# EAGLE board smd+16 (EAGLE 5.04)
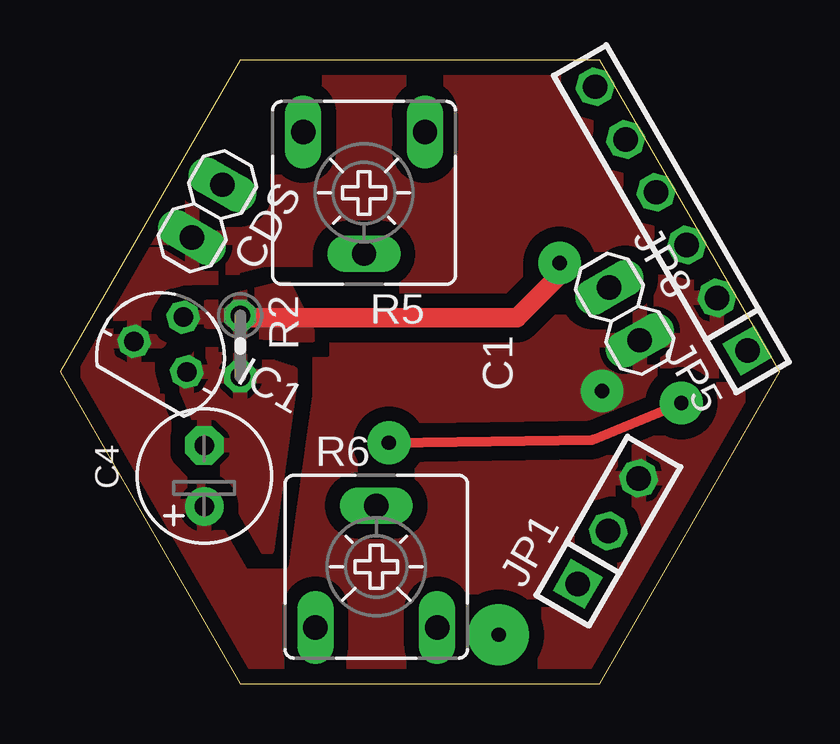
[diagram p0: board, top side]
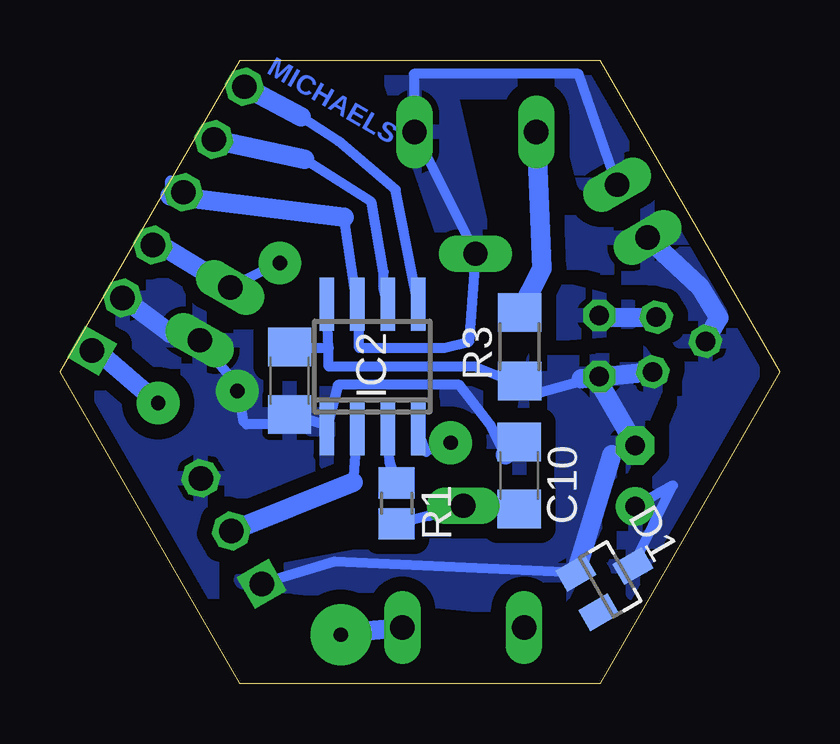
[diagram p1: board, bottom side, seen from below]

Size 30 x 25.98 mm. Coordinates in mm from the lower left corner, seen from the top.
Outline: 7.5,0 22.5,0 30,12.99 22.5,25.98 7.5,25.98 0,12.99 7.5,0
Copper layers (1*16): Top 0.035mm / dielectric 1.5mm / Bottom 0.035mm
Design rules "default *": minimum track width 10mil, minimum drill 24mil, track to track 8mil, track to pad 8mil, pad to pad 8mil, via to via 8mil, smd to smd 8mil, copper to edge 10mil, drill to drill 8mil, minimum pad ring 10mil, minimum via ring 8mil, stop-mask expansion 4mil, vias tented up to drill 0mil, thermal gap 10mil

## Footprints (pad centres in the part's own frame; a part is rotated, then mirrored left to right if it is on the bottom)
C1206 = smd 1.6 x 1.8: 1 -1.4,0; 2 1.4,0
E2,5-6 = drill 0.813 pad 1.6 round: + -1.27,0 | drill 0.813 pad 1.6 octagon: - 1.27,0
1X02 = drill 1.016 long: 1 -1.27,0; 2 1.27,0
SOT23 = smd 1 x 1.4: 1 -0.95,-1.1; 2 0.95,-1.1; 3 0,1.1
79LXX = drill 0.813 octagon: GND -1.27,0; IN 0,1.905; OUT 1.27,0
SO-08 = smd 0.6 x 2.2: 1 -1.905,-2.6; 2 -0.635,-2.6; 3 0.635,-2.6; 4 1.905,-2.6; 5 1.905,2.6; 6 0.635,2.6; 7 -0.635,2.6; 8 -1.905,2.6
1X03 = drill 1.016 square: 1 -2.54,0 | drill 1.016 octagon: 2 0,0; 3 2.54,0
1X06 = drill 1.016 square: 1 -6.35,0 | drill 1.016 octagon: 2 -3.81,0; 3 -1.27,0; 4 1.27,0; 5 3.81,0; 6 6.35,0
R0805 = smd 1.3 x 1.5: 1 -0.85,0; 2 0.85,0
0204V = drill 0.813 octagon: 1 -1.27,0; 2 1.27,0
R1206 = smd 1.6 x 1.803: 1 -1.422,0; 2 1.422,0
CA6V = drill 1.016 long: A -2.54,-2.54; E 2.54,-2.54; S 0,2.54

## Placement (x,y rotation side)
C1  0u1  [C1206]  20.42,12.62 270 bottom
C4  47u 10  [E2,5-6]  6.02,8.65 90 top
C10  0u1  [C1206]  10.85,8.66 270 bottom
CDS  [1X02]  6.14,19.68 240 top
D1  [SOT23]  7.06,4.34 300 bottom
IC1  [79LXX]  4.19,13.62 330 top
IC2  PIC12F629SN  [SO-08]  16.98,13.2 0 bottom
JP1  [1X03]  22.86,6.35 60 top
JP5  [1X06]  25.48,19.37 120 top
JP8  [1X02]  23.54,15.4 300 top
R1  150k  [R0805]  15.96,7.51 270 bottom
R2  150k  [0204V]  7.51,14.06 270 top
R3  680k  [R1206]  10.84,14.03 90 bottom
R5  500k  [CA6V]  12.68,20.45 180 top
R6  [CA6V]  13.19,4.87 0 top

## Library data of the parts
C1 C4 C10 R1-R3 = rcl
CDS JP8 = pinhead
D1 = diode-1
IC1 = v-reg
IC2 = microchip-3
JP1 JP5 = pinhead(2)
R5 R6 = pot

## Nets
CDS: IC2.2 JP1.2
N$1: C10.2 R1.2 R6.S
N$2: IC2.5 JP5.6
N$3: IC2.4 JP5.1
N$4: CDS.1 IC2.7 JP5.4 R5.A R5.S
N$5: R3.2 R5.E
N$7: R6.E
N$8: IC2.3 R1.1
N$10: IC1.IN JP5.3 JP8.1 R2.1
N$15: IC2.6 JP5.5
V+: C1.2 C4.+ C10.1 CDS.2 D1.3 IC1.GND IC2.1 JP1.3 JP5.2 JP8.2
V-: C1.1 C4.- D1.1 IC1.OUT IC2.8 JP1.1 R2.2 R3.1

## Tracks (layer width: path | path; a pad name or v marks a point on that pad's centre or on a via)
CDS
  Bottom 0.406: IC2.2 17.78,8.38
  Bottom 0.813: 17.78,8.38 JP1.2
N$1
  Bottom 0.406: 14.61,6.99 R6.S | C10.2 14.61,6.99 | 14.61,6.99 R1.2
N$2
  Bottom 0.406: 19.94,23.62 18.41,22.61 16,20.57 IC2.5
  Bottom 0.813: 19.94,23.62 JP5.6
N$3  (via drill 0.6 pad 1.78)
  Top 0.406: v13.72,10.03 22.23,10.16 v25.91,11.68
  Bottom 0.406: IC2.4 14.73,9.65 v13.72,10.03 | 28.57,13.97 JP5.1
  Bottom 0.813: v25.91,11.68 28.57,13.97
N$4
  Bottom 0.406: 18.16,19.43 IC2.7 17.53,14.86 17.53,13.97 13.97,13.97 12.95,14.22 R5.S R5.A 15.24,25.4 8.38,25.4 CDS.1 | 25.4,20.32 25.4,20.95 24.77,20.32 JP5.4
  Bottom 0.813: 18.16,19.43 25.4,20.32
  pour Bottom (isolate 0.61): 5.08,22.86 8.38,26.16 16.51,25.91 13.72,17.78 12.19,18.03 13.72,24.64 9.14,24.64 8.13,20.83
N$5
  Bottom 0.813: R3.2 9.91,17.27 R5.E
N$7
  Bottom 0.813: R6.E 17.65,2.16
N$8
  Bottom 0.406: IC2.3 16.26,9.27 R1.1
N$10  (via drill 0.6 pad 1.78)
  Top 0.406: R2.1 7.62,15.24
  Top 0.813: 7.62,15.24 19.05,15.24 20.83,17.02 v20.83,17.53
  Bottom 0.406: 26.04,18.41 JP5.3 | 7.62,15.24 R2.1 | JP8.1 v20.83,17.53 20.83,17.02
  Bottom 0.813: JP8.1 26.04,18.41 | IC1.IN 7.62,15.24
  pour Bottom (isolate 0.61): 5.33,15.49 6.86,14.73 10.41,14.48 9.4,16.51
  pour Top (isolate 0.61): 5.33,15.49 6.86,14.73 10.41,14.48 9.4,16.51
N$11  (via drill 0.6 pad 2.54)
  other vias: 18.29,2.03
N$15
  Bottom 0.406: 19.81,21.84 17.02,20.07 16.51,17.14 16.51,16.51 IC2.6
  Bottom 0.813: 19.81,21.84 JP5.5
V+  (via drill 0.6 pad 1.78)
  Bottom 0.406: 11.43,9.53 12.06,10.79 13.34,12.45 18.41,12.45 IC2.1 19.05,10.79 C1.2 20.32,10.79 22.23,10.79 22.35,10.92 22.61,12.45 JP8.2 25.4,14.48 25.4,14.61 | C4.+ 4.45,8.26 D1.3
  Bottom 0.813: 25.4,14.61 JP5.2 | C10.1 11.43,9.53 | CDS.2 3.3,16.51 2.54,15.24 IC1.GND
  other vias: 22.61,12.19
  pour Bottom (isolate 0.61, rank 6): 7.62,25.4 22.86,25.4 29.72,12.95 22.1,0.25 7.87,0.25 0.76,13.21
  pour Top (isolate 0.61, rank 6): 7.62,25.4 22.86,25.4 29.72,12.95 22.1,0.25 7.87,0.25 0.76,13.21
V-
  Bottom 0.406: 18.8,13.97 IC2.8 | C1.1 20.32,13.97 18.8,13.97 | R2.2 8.26,12.7 | R2.2 10,12.11 | 10,12.11 10.16,12.06 | 6.99,9.53 C4.- | 7.62,12.7 R2.2 | 18.8,13.97 18.8,13.21 12.7,13.21 10.25,12.21 | JP1.1 18.54,5.08 D1.1 | 10,12.11 10.25,12.21 | 10.25,12.21 R3.1
  Bottom 0.813: 8.26,12.7 IC1.OUT | D1.1 6.99,9.53 | C4.- 7.62,12.7
  pour Bottom (isolate 0.61, rank 2): 5.08,12.7 6.6,9.14 9.4,3.05 22.35,4.32 11.43,6.35 10.16,13.46 5.84,13.72
  pour Top (isolate 0.61, rank 2): 5.08,12.7 6.6,9.14 8.64,5.59 9.65,12.95 7.37,13.72 5.84,13.72

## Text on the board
Bottom: MICHAELS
